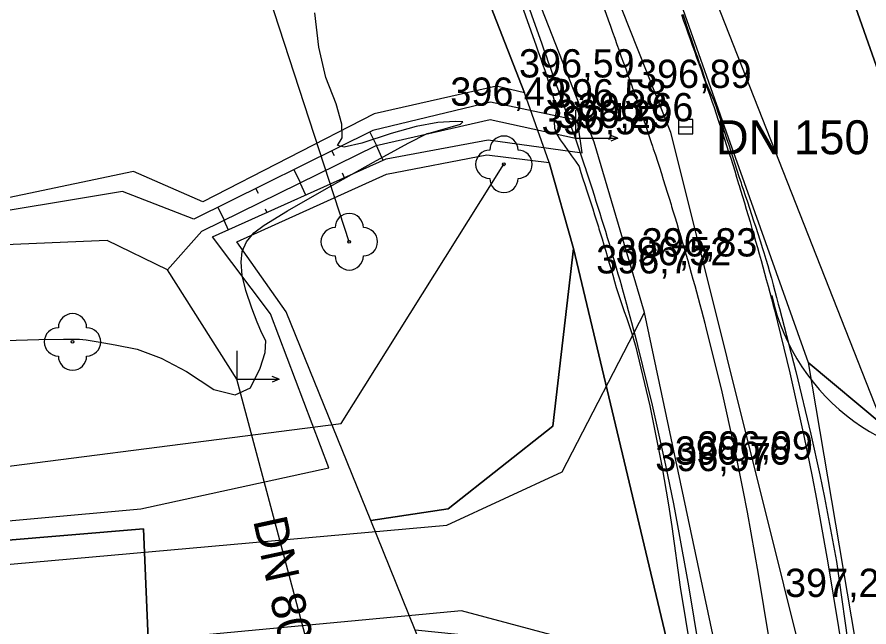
# Model space of a CAD drawing. Extents: x -574342 to -508101, y -1143544 to -1123894.
# Drawn here: x -508450.68 to -508420.54, y -1143259.23 to -1143237.66 of the extents above; entities that cross this region are included whole.
import ezdxf

# ---------------------------------------------------------------- set-up
doc = ezdxf.new("R2010")
doc.units = 0
for name, color, linetype in [('01_PARCELY_NAVRH_PC', 7, 'Continuous'), ('01_PARCELY_NAVRH_VHO', 7, 'Continuous'), ('01_PARCELY_NAVRH_ŽP', 7, 'Continuous'), ('05_VHO_V_TOK_STAV', 7, 'Continuous'), ('1000', 7, 'Continuous'), ('15', 7, 'Continuous'), ('21', 7, 'Continuous'), ('37', 7, 'Continuous'), ('52', 7, 'Continuous'), ('54', 7, 'Continuous'), ('55', 7, 'Continuous'), ('60', 7, 'Continuous'), ('61', 7, 'Continuous'), ('cesty', 7, 'Continuous'), ('Level 255', 7, 'Continuous'), ('VRST VEDL', 7, 'Continuous')]:
    doc.layers.add(name, color=color, linetype=linetype)

msp = doc.modelspace()

# ---------------------------------------------------------------- linework, layer by layer
at = {"layer": '01_PARCELY_NAVRH_PC'}
for points in [[(-508451.57, -1143168.14), (-508437.66, -1143207.58), (-508425.52, -1143241.92), (-508422.7, -1143249.88), (-508420.08, -1143265.35), (-508416.18, -1143288.91), (-508414.34, -1143296.2), (-508410.3, -1143304.94), (-508406.96, -1143310.33), (-508402.64, -1143313.55), (-508394.5, -1143317.14), (-508397.53, -1143325.93), (-508402.47, -1143323.55), (-508407.39, -1143320.93), (-508414.82, -1143312.69), (-508418.17, -1143303.49), (-508422.28, -1143289.33), (-508426.41, -1143265.09), (-508431, -1143245.85), (-508431.86, -1143242.81), (-508432.73, -1143240.34), (-508445.99, -1143206.42), (-508454.33, -1143183.49)], [(-508109.096, -1143172.158), (-508188.91, -1143212.74), (-508197.69, -1143215.86), (-508325.49, -1143244.3), (-508415.56, -1143252.78), (-508417.38, -1143252.95), (-508420.04, -1143252.1), (-508422.7, -1143249.88), (-508420.08, -1143265.35), (-508419.24, -1143259.91), (-508414.23, -1143256.72), (-508401.25, -1143255.47), (-508381.42, -1143253.61), (-508325.37, -1143248.48), (-508191.76, -1143218.68), (-508109.096, -1143176.822)]]:
    msp.add_lwpolyline(points, dxfattribs=at)
for points in [[(-508431, -1143245.85), (-508426.41, -1143265.09), (-508429.75, -1143260.04), (-508436.6, -1143259.34), (-508438.17, -1143255.47), (-508435.43, -1143255.05), (-508431.73, -1143252.13)], [(-508446.21, -1143255.76), (-508469.74, -1143257.73), (-508480.76, -1143258.08), (-508496.39, -1143258.35), (-508520.28, -1143255.11), (-508526.55, -1143254.9), (-508531.16, -1143250.06), (-508524.26, -1143263.08), (-508521.01, -1143259.29), (-508514.56, -1143259.91), (-508493.5, -1143263.3), (-508475.11, -1143263.39), (-508446.02, -1143260.22)]]:
    msp.add_lwpolyline(points, close=True, dxfattribs=at)
at = {"layer": '01_PARCELY_NAVRH_VHO'}
msp.add_lwpolyline([(-508469.74, -1143257.73), (-508446.21, -1143255.76), (-508446.02, -1143260.22), (-508445.4, -1143275.01), (-508441.9, -1143297.61), (-508434.31, -1143320.59), (-508432.21, -1143324.29), (-508414.59, -1143317.71), (-508420.1, -1143305.91), (-508426.78, -1143287.77), (-508433.97, -1143265.8), (-508436.6, -1143259.34), (-508438.17, -1143255.47), (-508441.16, -1143248.09), (-508442.91, -1143245.61), (-508437.61, -1143243.22), (-508434.06, -1143242.54), (-508431.86, -1143242.81), (-508432.73, -1143240.34), (-508433.72, -1143240.11), (-508438.05, -1143241.09), (-508444.11, -1143244.2), (-508446.56, -1143243.12), (-508452.58, -1143244.39)], dxfattribs=at)
at = {"layer": '01_PARCELY_NAVRH_ŽP'}
for points in [[(-508476.398, -1143116.058), (-508474.05, -1143124.14), (-508467.92, -1143139.18), (-508459.97, -1143152.33), (-508456.09, -1143158.71), (-508451.57, -1143168.14), (-508437.66, -1143207.58), (-508425.52, -1143241.92), (-508422.7, -1143249.88), (-508420.04, -1143252.1), (-508417.38, -1143252.95), (-508415.56, -1143252.78), (-508448.24, -1143160.16), (-508453.75, -1143145.01), (-508465.11, -1143123.03), (-508467.879, -1143116.058)], [(-508467.879, -1143116.058), (-508465.11, -1143123.03), (-508453.75, -1143145.01), (-508448.24, -1143160.16), (-508415.56, -1143252.78), (-508437, -1143116.058)]]:
    msp.add_lwpolyline(points, dxfattribs=at)
for points in [[(-508455.43, -1143236.54), (-508453.14, -1143234.1), (-508452.04, -1143229.57), (-508450.69, -1143221.56), (-508452.8, -1143209.75), (-508452.72, -1143198.2), (-508454.33, -1143183.49), (-508445.99, -1143206.42), (-508432.73, -1143240.34), (-508433.72, -1143240.11), (-508438.05, -1143241.09), (-508444.11, -1143244.2), (-508446.56, -1143243.12), (-508452.58, -1143244.39)], [(-508442.91, -1143245.61), (-508437.61, -1143243.22), (-508434.06, -1143242.54), (-508431.86, -1143242.81), (-508431, -1143245.85), (-508431.73, -1143252.13), (-508435.43, -1143255.05), (-508438.17, -1143255.47), (-508441.16, -1143248.09)]]:
    msp.add_lwpolyline(points, close=True, dxfattribs=at)
at = {"layer": '05_VHO_V_TOK_STAV'}
msp.add_lwpolyline([(-508396.743, -1143399.678), (-508414.306, -1143332.655), (-508430.208, -1143292.193), (-508438.98, -1143265.17), (-508442.91, -1143250.47), (-508445.36, -1143246.6), (-508447.49, -1143245.57), (-508453.89, -1143245.84)], dxfattribs=at)
at = {"layer": '1000'}
for points in [[(-508437.122, -1143224.571), (-508432.123, -1143238.605), (-508432.045, -1143238.821), (-508431.968, -1143239.038), (-508431.891, -1143239.254), (-508431.814, -1143239.471), (-508431.737, -1143239.687), (-508431.66, -1143239.904), (-508431.583, -1143240.12), (-508431.506, -1143240.336), (-508431.429, -1143240.553), (-508431.351, -1143240.769), (-508431.282, -1143240.965), (-508431.275, -1143240.985), (-508431.2, -1143241.196), (-508431.125, -1143241.408), (-508431.051, -1143241.619), (-508430.978, -1143241.831), (-508430.905, -1143242.043), (-508430.833, -1143242.255), (-508430.761, -1143242.467), (-508430.689, -1143242.679), (-508430.618, -1143242.891), (-508430.575, -1143243.02), (-508430.548, -1143243.104), (-508430.478, -1143243.317), (-508430.408, -1143243.53), (-508430.339, -1143243.743), (-508430.27, -1143243.956), (-508430.202, -1143244.17), (-508430.135, -1143244.383), (-508430.068, -1143244.597), (-508430.001, -1143244.811), (-508429.935, -1143245.025), (-508429.915, -1143245.091), (-508429.869, -1143245.239), (-508429.804, -1143245.453), (-508429.74, -1143245.668), (-508429.676, -1143245.883), (-508429.612, -1143246.097), (-508429.549, -1143246.312), (-508429.486, -1143246.527), (-508429.424, -1143246.743), (-508429.362, -1143246.958), (-508429.301, -1143247.173), (-508429.301, -1143247.176), (-508429.241, -1143247.389), (-508429.18, -1143247.605), (-508429.121, -1143247.821), (-508429.062, -1143248.037), (-508429.003, -1143248.253), (-508428.945, -1143248.469), (-508428.887, -1143248.686), (-508428.83, -1143248.902), (-508428.773, -1143249.119), (-508428.733, -1143249.274), (-508428.212, -1143251.384), (-508427.739, -1143253.505), (-508427.46, -1143254.872), (-508427.313, -1143255.637), (-508426.934, -1143257.777), (-508425.8, -1143264.636)], [(-508437.307, -1143224.637), (-508432.319, -1143238.675), (-508432.242, -1143238.892), (-508432.165, -1143239.108), (-508432.089, -1143239.325), (-508432.016, -1143239.543), (-508431.946, -1143239.762), (-508431.876, -1143239.981), (-508431.807, -1143240.2), (-508431.737, -1143240.419), (-508431.668, -1143240.638), (-508431.599, -1143240.857), (-508431.625, -1143241.087), (-508431.629, -1143241.111), (-508431.677, -1143241.365), (-508431.668, -1143241.598), (-508431.591, -1143241.807), (-508431.466, -1143241.999), (-508431.331, -1143242.189), (-508431.197, -1143242.379), (-508431.062, -1143242.569), (-508430.929, -1143242.759), (-508430.802, -1143242.953), (-508430.759, -1143243.081), (-508430.732, -1143243.165), (-508430.663, -1143243.378), (-508430.593, -1143243.59), (-508430.524, -1143243.803), (-508430.455, -1143244.015), (-508430.386, -1143244.228), (-508430.318, -1143244.441), (-508430.25, -1143244.654), (-508430.184, -1143244.867), (-508430.117, -1143245.081), (-508430.097, -1143245.147), (-508430.052, -1143245.295), (-508429.986, -1143245.508), (-508429.922, -1143245.723), (-508429.858, -1143245.937), (-508429.794, -1143246.151), (-508429.732, -1143246.366), (-508429.669, -1143246.58), (-508429.608, -1143246.795), (-508429.547, -1143247.01), (-508429.486, -1143247.226), (-508429.485, -1143247.228), (-508429.42, -1143247.439), (-508429.345, -1143247.651), (-508429.272, -1143247.862), (-508429.199, -1143248.074), (-508429.126, -1143248.286), (-508429.054, -1143248.499), (-508428.983, -1143248.711), (-508428.912, -1143248.924), (-508428.847, -1143249.138), (-508428.808, -1143249.293), (-508428.301, -1143251.405), (-508427.873, -1143253.534), (-508427.631, -1143254.906), (-508427.514, -1143255.675), (-508427.224, -1143257.825), (-508426.094, -1143264.685)], [(-508427.181, -1143237.576), (-508427.104, -1143237.793), (-508427.027, -1143238.009), (-508426.95, -1143238.226), (-508426.873, -1143238.442), (-508426.796, -1143238.659), (-508426.719, -1143238.875), (-508426.641, -1143239.091), (-508426.572, -1143239.287), (-508426.564, -1143239.308), (-508426.485, -1143239.53), (-508426.407, -1143239.752), (-508426.329, -1143239.975), (-508426.252, -1143240.197), (-508426.176, -1143240.42), (-508426.099, -1143240.643), (-508426.024, -1143240.866), (-508425.949, -1143241.089), (-508425.874, -1143241.312), (-508425.829, -1143241.447), (-508425.8, -1143241.536), (-508425.726, -1143241.76), (-508425.653, -1143241.983), (-508425.581, -1143242.207), (-508425.509, -1143242.432), (-508425.437, -1143242.656), (-508425.366, -1143242.881), (-508425.295, -1143243.105), (-508425.225, -1143243.33), (-508425.156, -1143243.555), (-508425.135, -1143243.624), (-508425.087, -1143243.78), (-508425.019, -1143244.006), (-508424.951, -1143244.231), (-508424.883, -1143244.457), (-508424.816, -1143244.683), (-508424.75, -1143244.909), (-508424.684, -1143245.135), (-508424.619, -1143245.361), (-508424.554, -1143245.587), (-508424.49, -1143245.814), (-508424.489, -1143245.816), (-508424.426, -1143246.041), (-508424.363, -1143246.267), (-508424.3, -1143246.494), (-508424.238, -1143246.722), (-508424.176, -1143246.949), (-508424.115, -1143247.176), (-508424.054, -1143247.404), (-508423.994, -1143247.631), (-508423.934, -1143247.859), (-508423.892, -1143248.022), (-508423.345, -1143250.24), (-508422.847, -1143252.47), (-508422.554, -1143253.907), (-508422.399, -1143254.711), (-508422.001, -1143256.961), (-508420.867, -1143263.821)], [(-508427.135, -1143237.56), (-508427.061, -1143237.777), (-508426.987, -1143237.995), (-508426.912, -1143238.212), (-508426.838, -1143238.43), (-508426.763, -1143238.647), (-508426.688, -1143238.864), (-508426.613, -1143239.081), (-508426.546, -1143239.277), (-508426.538, -1143239.299), (-508426.462, -1143239.522), (-508426.386, -1143239.745), (-508426.31, -1143239.968), (-508426.216, -1143240.185), (-508426.124, -1143240.402), (-508426.031, -1143240.619), (-508425.953, -1143240.842), (-508425.875, -1143241.064), (-508425.799, -1143241.287), (-508425.755, -1143241.423), (-508425.725, -1143241.511), (-508425.652, -1143241.735), (-508425.579, -1143241.959), (-508425.506, -1143242.183), (-508425.434, -1143242.408), (-508425.362, -1143242.632), (-508425.29, -1143242.857), (-508425.219, -1143243.081), (-508425.146, -1143243.306), (-508425.071, -1143243.529), (-508425.048, -1143243.598), (-508424.996, -1143243.752), (-508424.921, -1143243.976), (-508424.846, -1143244.2), (-508424.772, -1143244.424), (-508424.698, -1143244.648), (-508424.624, -1143244.872), (-508424.55, -1143245.096), (-508424.477, -1143245.32), (-508424.405, -1143245.545), (-508424.332, -1143245.769), (-508424.331, -1143245.772), (-508424.26, -1143245.994), (-508424.188, -1143246.219), (-508424.123, -1143246.446), (-508424.061, -1143246.673), (-508423.998, -1143246.901), (-508423.936, -1143247.128), (-508423.874, -1143247.356), (-508423.813, -1143247.584), (-508423.752, -1143247.812), (-508423.708, -1143247.974), (-508423.137, -1143250.192), (-508422.599, -1143252.418), (-508422.277, -1143253.853), (-508422.116, -1143254.658), (-508421.696, -1143256.911), (-508420.73, -1143263.798)]]:
    msp.add_lwpolyline(points, dxfattribs=at)
at = {"layer": '21'}
msp.add_lwpolyline([(-508434.767, -1143223.732), (-508429.767, -1143237.766), (-508429.69, -1143237.982), (-508429.613, -1143238.199), (-508429.536, -1143238.415), (-508429.459, -1143238.632), (-508429.382, -1143238.848), (-508429.305, -1143239.065), (-508429.228, -1143239.281), (-508429.151, -1143239.497), (-508429.074, -1143239.714), (-508428.996, -1143239.93), (-508428.927, -1143240.126), (-508428.919, -1143240.147), (-508428.843, -1143240.363), (-508428.766, -1143240.58), (-508428.69, -1143240.797), (-508428.615, -1143241.014), (-508428.54, -1143241.231), (-508428.466, -1143241.449), (-508428.392, -1143241.666), (-508428.319, -1143241.884), (-508428.246, -1143242.102), (-508428.202, -1143242.234), (-508428.174, -1143242.32), (-508428.102, -1143242.538), (-508428.031, -1143242.757), (-508427.96, -1143242.975), (-508427.889, -1143243.194), (-508427.82, -1143243.413), (-508427.75, -1143243.632), (-508427.682, -1143243.851), (-508427.613, -1143244.07), (-508427.546, -1143244.29), (-508427.525, -1143244.358), (-508427.478, -1143244.51), (-508427.411, -1143244.73), (-508427.345, -1143244.949), (-508427.279, -1143245.17), (-508427.214, -1143245.39), (-508427.149, -1143245.61), (-508427.085, -1143245.831), (-508427.021, -1143246.052), (-508426.958, -1143246.273), (-508426.895, -1143246.494), (-508426.895, -1143246.496), (-508426.833, -1143246.715), (-508426.771, -1143246.936), (-508426.71, -1143247.158), (-508426.65, -1143247.379), (-508426.589, -1143247.601), (-508426.53, -1143247.823), (-508426.471, -1143248.045), (-508426.412, -1143248.267), (-508426.354, -1143248.489), (-508426.313, -1143248.648), (-508425.779, -1143250.812), (-508425.293, -1143252.988), (-508425.007, -1143254.39), (-508424.856, -1143255.174), (-508424.468, -1143257.369), (-508423.333, -1143264.228)], dxfattribs=at)
at = {"layer": '37'}
for points in [[(-508473.82, -1143129.8), (-508468.34, -1143141.31), (-508458.53, -1143158.76), (-508453.13, -1143170.86), (-508439.96, -1143210.5), (-508427.56, -1143241.73), (-508421.57, -1143265.72), (-508416.35, -1143292.6), (-508412.42, -1143304.7), (-508408.82, -1143311.83)], [(-508473.82, -1143129.8), (-508468.34, -1143141.31), (-508458.53, -1143158.76), (-508453.13, -1143170.86), (-508439.96, -1143210.5), (-508427.56, -1143241.73), (-508421.57, -1143265.72), (-508416.35, -1143292.6), (-508412.42, -1143304.7), (-508408.82, -1143311.83)], [(-508408.82, -1143311.83), (-508404.37, -1143317.04), (-508398.21, -1143321.18), (-508393.66, -1143322.44), (-508393.79, -1143324.58), (-508400.56, -1143323.11), (-508406.32, -1143319.06), (-508411.41, -1143313.16), (-508415.31, -1143305.9), (-508419.33, -1143292.88), (-508424.96, -1143264.72), (-508428.49, -1143248.11), (-508430.27, -1143242.09), (-508442.28, -1143211.48), (-508455.59, -1143171.17), (-508460.82, -1143160.05), (-508470.5, -1143142.85)], [(-508408.82, -1143311.83), (-508404.37, -1143317.04), (-508398.21, -1143321.18), (-508393.66, -1143322.44), (-508393.79, -1143324.58), (-508400.56, -1143323.11), (-508406.32, -1143319.06), (-508411.41, -1143313.16), (-508415.31, -1143305.9), (-508419.33, -1143292.88), (-508424.96, -1143264.72), (-508428.49, -1143248.11), (-508430.27, -1143242.09), (-508442.28, -1143211.48), (-508455.59, -1143171.17), (-508460.82, -1143160.05), (-508470.5, -1143142.85)], [(-508442.91, -1143250.47), (-508445.36, -1143246.6), (-508447.49, -1143245.57), (-508453.89, -1143245.84), (-508456.96, -1143238.4), (-508458.75, -1143235.83)], [(-508442.91, -1143250.47), (-508445.36, -1143246.6), (-508447.49, -1143245.57), (-508453.89, -1143245.84), (-508456.96, -1143238.4), (-508458.75, -1143235.83)]]:
    msp.add_lwpolyline(points, dxfattribs=at)
at = {"layer": '52'}
for p, q in [((-508430.93, -1143240.95), (-508430.93, -1143241.95)), ((-508427.28, -1143241.54), (-508426.78, -1143241.54)), ((-508430.93, -1143241.95), (-508429.43, -1143241.95)), ((-508429.43, -1143241.95), (-508429.68, -1143241.85)), ((-508429.43, -1143241.95), (-508429.68, -1143242.05)), ((-508442.91, -1143249.47), (-508442.91, -1143250.47)), ((-508442.91, -1143250.47), (-508441.41, -1143250.47)), ((-508441.41, -1143250.47), (-508441.66, -1143250.37)), ((-508441.41, -1143250.47), (-508441.66, -1143250.57))]:
    msp.add_line(p, q, dxfattribs=at)
msp.add_lwpolyline([(-508427.28, -1143241.79), (-508426.78, -1143241.79), (-508426.78, -1143241.29), (-508427.28, -1143241.29)], close=True, dxfattribs=at)
at = {"layer": '54'}
for centre in [(-508433.46, -1143242.87), (-508438.93, -1143245.61), (-508448.72, -1143249.15)]:
    msp.add_circle(centre, 0.05, dxfattribs=at)
for centre, start, end in [((-508433.46, -1143242.37), 0, 180), ((-508433.96, -1143242.87), 90, 270), ((-508432.96, -1143242.87), 270, 90), ((-508433.46, -1143243.37), 180, 0), ((-508438.93, -1143245.11), 0, 180), ((-508439.43, -1143245.61), 90, 270), ((-508438.43, -1143245.61), 270, 90), ((-508438.93, -1143246.11), 180, 0), ((-508448.72, -1143248.65), 0, 180), ((-508449.22, -1143249.15), 90, 270), ((-508448.22, -1143249.15), 270, 90), ((-508448.72, -1143249.65), 180, 0)]:
    msp.add_arc(centre, 0.5, start, end, dxfattribs=at)
at = {"layer": '55'}
msp.add_line((-508438.93, -1143245.61), (-508453.34, -1143201.44), dxfattribs=at)
msp.add_line((-508438.93, -1143245.61), (-508453.34, -1143201.44), dxfattribs=at)
for points in [[(-508410.24, -1143298.34), (-508420.04, -1143252.1), (-508438.58, -1143205.02)], [(-508410.24, -1143298.34), (-508420.04, -1143252.1), (-508438.58, -1143205.02)], [(-508471.18, -1143256.14), (-508439.22, -1143252.04), (-508433.46, -1143242.87)], [(-508471.18, -1143256.14), (-508439.22, -1143252.04), (-508433.46, -1143242.87)], [(-508495.48, -1143259.17), (-508472.43, -1143258.93), (-508435.48, -1143255.63), (-508431.4, -1143253.75), (-508428.49, -1143248.11)], [(-508495.48, -1143259.17), (-508472.43, -1143258.93), (-508435.48, -1143255.63), (-508431.4, -1143253.75), (-508428.49, -1143248.11)], [(-508424.96, -1143264.72), (-508430.77, -1143259.78), (-508434.96, -1143258.66), (-508472.39, -1143262.17), (-508495.8, -1143262.63)], [(-508424.96, -1143264.72), (-508430.77, -1143259.78), (-508434.96, -1143258.66), (-508472.39, -1143262.17), (-508495.8, -1143262.63)]]:
    msp.add_lwpolyline(points, dxfattribs=at)
at = {"layer": '60'}
for points in [[(-508480.22, -1143257.91), (-508469.09, -1143257.11), (-508446.3, -1143255.05), (-508439.65, -1143253.6), (-508441.71, -1143248.16), (-508443.77, -1143245.44), (-508437.62, -1143242.68), (-508434.01, -1143242.01), (-508430.69, -1143242.47), (-508430.86, -1143241.32), (-508433.93, -1143240.67), (-508438.09, -1143241.68), (-508444.43, -1143244.81), (-508446.95, -1143243.83), (-508452.85, -1143244.81)], [(-508480.22, -1143257.91), (-508469.09, -1143257.11), (-508446.3, -1143255.05), (-508439.65, -1143253.6), (-508441.71, -1143248.16), (-508443.77, -1143245.44), (-508437.62, -1143242.68), (-508434.01, -1143242.01), (-508430.69, -1143242.47), (-508430.86, -1143241.32), (-508433.93, -1143240.67), (-508438.09, -1143241.68), (-508444.43, -1143244.81), (-508446.95, -1143243.83), (-508452.85, -1143244.81)], [(-508445.36, -1143246.6), (-508444.15, -1143245.24), (-508437.98, -1143242.2), (-508433.95, -1143241.28), (-508430.93, -1143241.95)], [(-508445.36, -1143246.6), (-508444.15, -1143245.24), (-508437.98, -1143242.2), (-508433.95, -1143241.28), (-508430.93, -1143241.95)]]:
    msp.add_lwpolyline(points, dxfattribs=at)
at = {"layer": '61'}
for p, q in [((-508438.198, -1143241.739), (-508437.97, -1143242.2)), ((-508438.198, -1143241.739), (-508437.97, -1143242.2)), ((-508437.731, -1143242.73), (-508437.97, -1143242.2)), ((-508437.731, -1143242.73), (-508437.97, -1143242.2)), ((-508439.543, -1143242.404), (-508439.467, -1143242.558)), ((-508439.543, -1143242.404), (-508439.467, -1143242.558)), ((-508440.887, -1143243.07), (-508440.659, -1143243.529)), ((-508440.887, -1143243.07), (-508440.659, -1143243.529)), ((-508439.098, -1143243.347), (-508439.171, -1143243.186)), ((-508439.098, -1143243.347), (-508439.171, -1143243.186)), ((-508440.465, -1143243.964), (-508440.661, -1143243.53)), ((-508440.465, -1143243.964), (-508440.661, -1143243.53)), ((-508442.231, -1143243.736), (-508442.155, -1143243.888)), ((-508442.231, -1143243.736), (-508442.155, -1143243.888)), ((-508443.575, -1143244.402), (-508443.349, -1143244.859)), ((-508443.575, -1143244.402), (-508443.349, -1143244.859)), ((-508441.833, -1143244.581), (-508441.891, -1143244.452)), ((-508441.833, -1143244.581), (-508441.891, -1143244.452)), ((-508443.2, -1143245.197), (-508443.352, -1143244.861)), ((-508443.2, -1143245.197), (-508443.352, -1143244.861))]:
    msp.add_line(p, q, dxfattribs=at)
at = {"layer": 'cesty'}
for centre, start, end in [((-508416.659, -1143245.893), 192.4584, 275.3361), ((-508413.198, -1143263.648), 95.3361, 192.4584)]:
    msp.add_arc(centre, 7.5, start, end, dxfattribs=at)
at = {"layer": 'VRST VEDL'}
msp.add_lwpolyline([(-508451.113, -1143249.099), (-508449.914, -1143249.065), (-508449.034, -1143249.05), (-508448.475, -1143249.053), (-508448.236, -1143249.075), (-508447.815, -1143249.142), (-508447.214, -1143249.253), (-508446.431, -1143249.409), (-508445.588, -1143249.725), (-508444.685, -1143250.2), (-508443.722, -1143250.834), (-508442.966, -1143251.025), (-508442.419, -1143250.772), (-508442.079, -1143250.075), (-508441.899, -1143249.521), (-508441.879, -1143249.109), (-508442.018, -1143248.84), (-508442.182, -1143248.455), (-508442.371, -1143247.954), (-508442.586, -1143247.337), (-508442.715, -1143246.798), (-508442.758, -1143246.336), (-508442.716, -1143245.953), (-508442.566, -1143245.607), (-508442.309, -1143245.297), (-508441.943, -1143245.025), (-508441.115, -1143244.517), (-508439.823, -1143243.772), (-508438.068, -1143242.792), (-508436.85, -1143242.127), (-508436.168, -1143241.778), (-508436.022, -1143241.743), (-508435.778, -1143241.676), (-508435.437, -1143241.577), (-508434.997, -1143241.446), (-508434.912, -1143241.372), (-508435.179, -1143241.354), (-508435.8, -1143241.392), (-508436.557, -1143241.533), (-508437.45, -1143241.776), (-508438.479, -1143242.123), (-508439.11, -1143242.264), (-508439.345, -1143242.202), (-508439.182, -1143241.935), (-508439.198, -1143241.446), (-508439.39, -1143240.735), (-508439.76, -1143239.803), (-508440.011, -1143238.73), (-508440.143, -1143237.518)], dxfattribs=at)

# ---------------------------------------------------------------- texts
at = {"layer": '15'}
msp.add_text('DN 150', height=1.2, dxfattribs=at).set_placement((-508425.961, -1143242.514))
msp.add_text('DN 150', height=1.2, dxfattribs=at).set_placement((-508425.961, -1143242.514))
msp.add_text('DN 800', height=1.2, rotation=282.2963, dxfattribs=at).set_placement((-508442.336, -1143255.463))
msp.add_text('DN 800', height=1.2, rotation=282.2963, dxfattribs=at).set_placement((-508442.336, -1143255.463))
at = {"layer": 'Level 255'}
for s, p in [('396,59', (-508432.925, -1143239.8)), ('396,89', (-508428.785, -1143240.17)), ('396,49', (-508435.355, -1143240.8)), ('396,58', (-508431.795, -1143240.86)), ('396,66', (-508430.845, -1143241.35)), ('396,55', (-508432.125, -1143241.81)), ('396,29', (-508431.605, -1143241.59)), ('396,83', (-508428.585, -1143246.13)), ('396,52', (-508429.505, -1143246.44)), ('396,77', (-508430.195, -1143246.73)), ('396,99', (-508426.615, -1143253.31)), ('396,76', (-508427.415, -1143253.49)), ('396,97', (-508428.105, -1143253.72)), ('397,29', (-508423.515, -1143258.17))]:
    msp.add_text(s, height=1, dxfattribs=at).set_placement(p)

doc.saveas('drawing.dxf')
